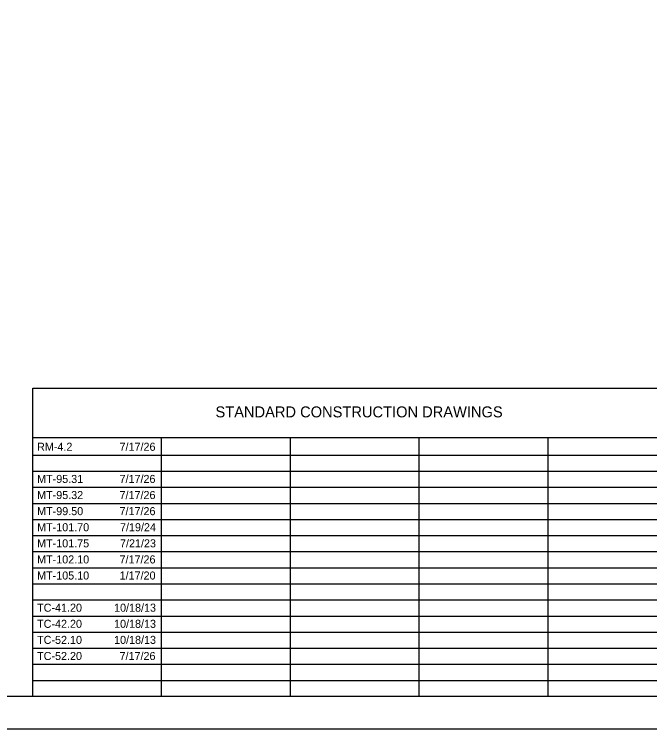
# Model space of a CAD drawing. Extents: x 0 to 34, y 0 to 22.
# Drawn here: x 9.86 to 19.73, y 0 to 11.1 of the extents above; entities that cross this region are included whole.
import ezdxf

# ---------------------------------------------------------------- set-up
doc = ezdxf.new("R2010")
doc.units = 0
for name, color, linetype in [('SH_Border', 7, 'Continuous'), ('SH_Cut_Line', 7, 'Continuous'), ('SH_Data', 7, 'Continuous'), ('SH_Text', 7, 'Continuous')]:
    doc.layers.add(name, color=color, linetype=linetype)

msp = doc.modelspace()

# ---------------------------------------------------------------- linework, layer by layer
at = {"layer": 'SH_Border'}
msp.add_lwpolyline([(1.5, 21.5), (33.5, 21.5), (33.5, 0.5), (1.5, 0.5)], close=True, dxfattribs=at)
at = {"layer": 'SH_Cut_Line'}
msp.add_lwpolyline([(0, 0), (34, 0), (34, 22), (0, 22)], close=True, dxfattribs=at)
at = {"layer": 'SH_Data'}
for p, q in [((10.15, 5.292), (23.6, 5.292)), ((10.15, 0.5), (10.15, 5.292)), ((10.15, 4.521), (23.6, 4.521)), ((12.15, 0.5), (12.15, 4.521)), ((14.15, 0.5), (14.15, 4.521)), ((16.15, 0.5), (16.15, 4.521)), ((18.15, 0.5), (18.15, 4.521)), ((10.15, 4.25), (23.6, 4.25)), ((10.15, 4), (23.6, 4)), ((10.15, 3.75), (23.6, 3.75)), ((10.15, 3.5), (23.6, 3.5)), ((10.15, 3.25), (23.6, 3.25)), ((10.15, 3), (23.6, 3)), ((10.15, 2.75), (23.6, 2.75)), ((10.15, 2.5), (23.6, 2.5)), ((10.15, 2.25), (23.6, 2.25)), ((10.15, 2), (23.6, 2)), ((10.15, 1.75), (23.6, 1.75)), ((10.15, 1.5), (23.6, 1.5)), ((10.15, 1.25), (23.6, 1.25)), ((10.15, 1), (23.6, 1)), ((10.15, 0.75), (23.6, 0.75))]:
    msp.add_line(p, q, dxfattribs=at)

# ---------------------------------------------------------------- texts
at = {"layer": 'SH_Text'}
for s, height, p in [('STANDARD CONSTRUCTION DRAWINGS', 0.17, (12.986, 4.836)), ('RM-4.2', 0.125, (10.217, 4.317)), ('7/17/26', 0.125, (11.497, 4.317)), ('MT-95.31', 0.125, (10.217, 3.817)), ('7/17/26', 0.125, (11.497, 3.817)), ('MT-95.32', 0.125, (10.217, 3.567)), ('7/17/26', 0.125, (11.497, 3.567)), ('MT-99.50', 0.125, (10.217, 3.317)), ('7/17/26', 0.125, (11.497, 3.317)), ('MT-101.70', 0.125, (10.217, 3.067)), ('7/19/24', 0.125, (11.504, 3.067)), ('MT-101.75', 0.125, (10.217, 2.817)), ('7/21/23', 0.125, (11.504, 2.817)), ('MT-102.10', 0.125, (10.217, 2.567)), ('7/17/26', 0.125, (11.497, 2.567)), ('MT-105.10', 0.125, (10.217, 2.317)), ('1/17/20', 0.125, (11.498, 2.317)), ('TC-41.20', 0.125, (10.217, 1.817)), ('10/18/13', 0.125, (11.412, 1.817)), ('TC-42.20', 0.125, (10.217, 1.567)), ('10/18/13', 0.125, (11.412, 1.567)), ('TC-52.10', 0.125, (10.217, 1.317)), ('10/18/13', 0.125, (11.412, 1.317)), ('TC-52.20', 0.125, (10.217, 1.067)), ('7/17/26', 0.125, (11.497, 1.067))]:
    msp.add_text(s, height=height, dxfattribs=at).set_placement(p)

doc.saveas('drawing.dxf')
